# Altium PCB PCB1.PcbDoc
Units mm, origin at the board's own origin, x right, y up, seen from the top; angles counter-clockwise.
Board outline 152.4 x 101.6 mm, 2 copper layers (Top Layer, Bottom Layer); 41 components, 50 nets, 187 pads, 0 vias.
Unrouted connection lines stored in the file: 128.
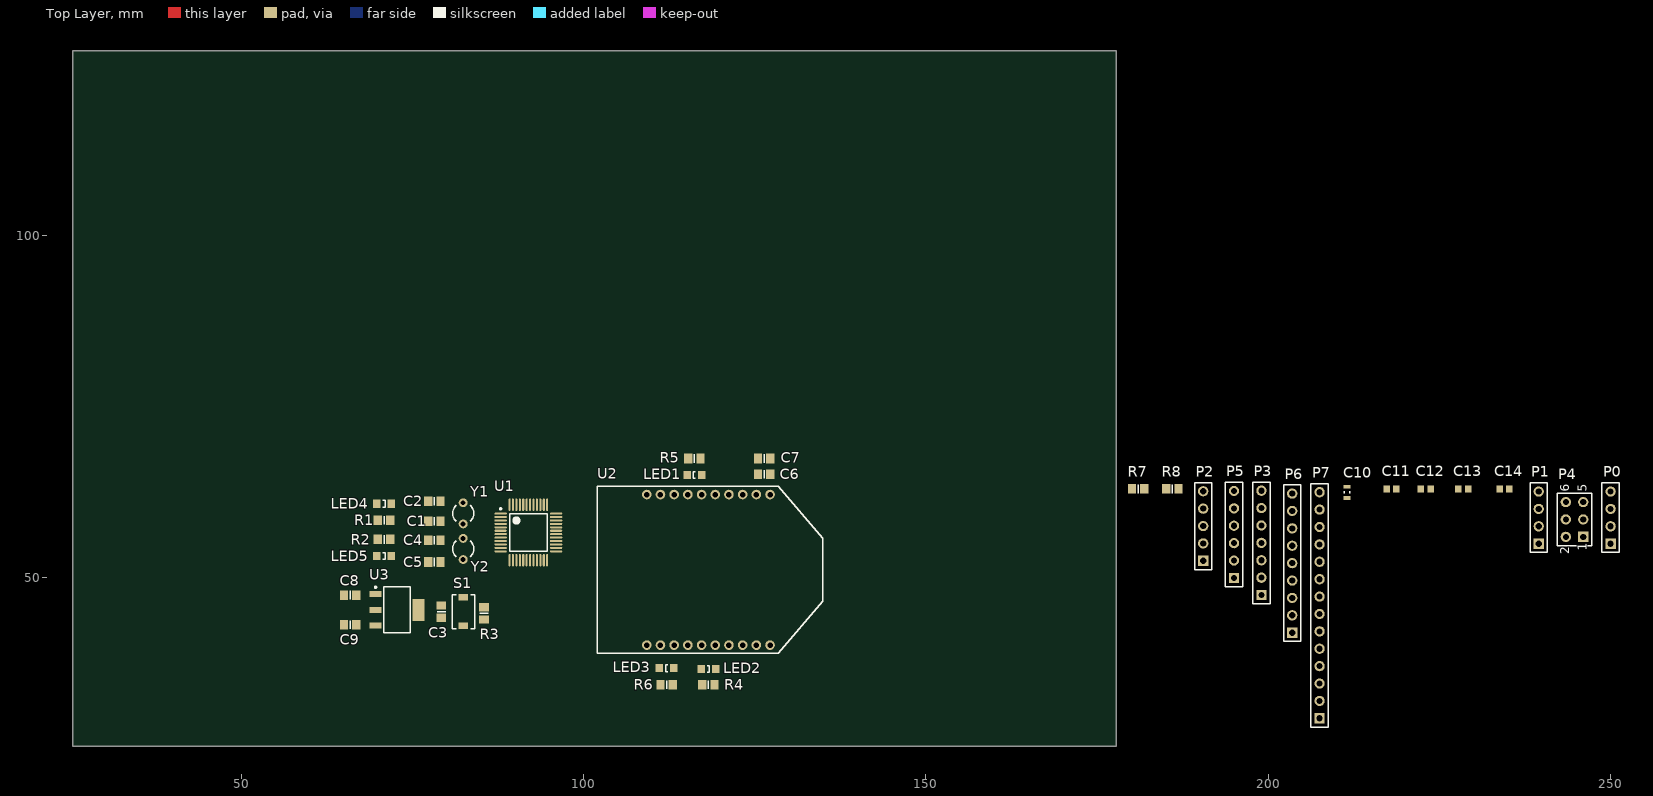
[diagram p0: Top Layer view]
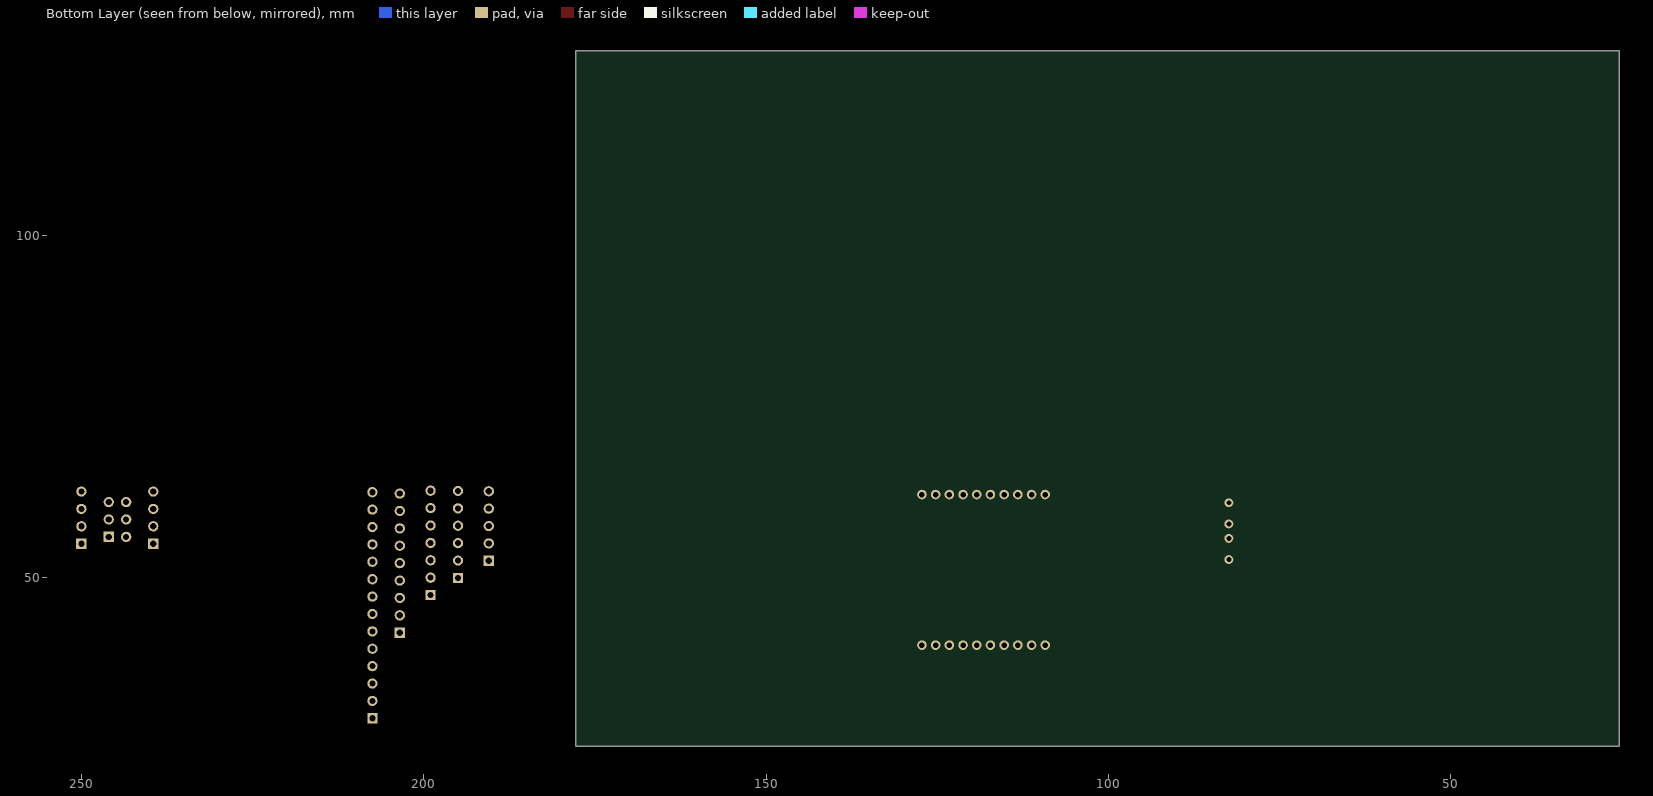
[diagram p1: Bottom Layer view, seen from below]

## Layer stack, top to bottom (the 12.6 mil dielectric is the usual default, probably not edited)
Top Solder: solder mask 0.0102, Solder Resist, Dk 3.5
Top Layer: signal copper 0.0356
Dielectric 1: dielectric 0.32, FR-4, Dk 4.8
Bottom Layer: signal copper 0.0356
Bottom Solder: solder mask 0.0102, Solder Resist, Dk 3.5

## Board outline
25.4,25.4 177.8,25.4 177.8,127 25.4,127

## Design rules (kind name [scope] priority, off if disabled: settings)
Clearance [All] p1: gap=0.254 ignorepadtopadclearanceinfootprint=FALSE except(0: Arc-Hole Track-Hole SMDPad-Hole THPad-Hole Via-Hole Fill-Hole Poly-Hole Region-Hole Text-Hole)
PolygonConnect [All] p1: connectstyle=Relief reliefconductorwidth=0.254 reliefentries=4 polygonreliefangle="90 Angle" airgapwidth=0.254
RoomDefinition Sheet1 [InComponentClass('Sheet1')] p1: confinementstyle=ConfineIn formatcopy=TRUE lockcomponents=FALSE outline 179,28 251.999,28 251.999,67 179,67
RoutingVias [All] p1: holewidth=0.711 width=1.27 viastyle="Through Hole" minholewidth=0.711 minwidth=1.27 maxholewidth=0.711 maxwidth=1.27
SolderMaskExpansion [All] p1: expansion=0.102
Width [All] p1: maxlimit=0.254 minlimit=0.254 preferedwidth=0.254
30 further rules are at their usual default settings.

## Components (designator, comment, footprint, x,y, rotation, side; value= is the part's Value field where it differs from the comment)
C1 "Cap" 6-0805_N 78.232,58.293 r180 top value=100pF
C2 "Cap" 6-0805_N 78.232,61.214 r180 top value=100pF
C3 "Cap" 6-0805_N 79.248,45.085 r90 top value=100pF
C4 "Cap" 6-0805_N 78.232,55.499 r0 top value=100pF
C5 "Cap" 6-0805_N 78.232,52.324 r0 top value=100pF
C6 "Cap" 6-0805_N 126.365,65.151 r0 top value=100pF
C7 "Cap" 6-0805_N 126.365,67.437 r0 top value=100pF
C8 "Cap" 6-0805_N 65.913,47.498 r0 top value=10uF
C9 "Cap" 6-0805_N 65.913,43.18 r0 top value=10uF
C10 "1 µF" CAPC1609X100X15NL20 211.5,62.5 r90 top
C11 "100 nF" SAMS-C0603-2_M 218,63 r0 top
C12 "100 nF" SAMS-C0603-2_M 223,63 r0 top
C13 "100 nF" SAMS-C0603-2_M 228.5,63 r0 top
C14 "100 nF" SAMS-C0603-2_M 234.5,63 r0 top
LED1 "150080SS75000" 0805_A 116.205,65.024 r0 top
LED2 "150080SS75000" 0805_A 118.237,36.703 r180 top
LED3 "150080SS75000" 0805_A 112.141,36.83 r0 top
LED4 "150080SS75000" 0805_A 70.866,60.833 r180 top
LED5 "150080SS75000" 0805_A 70.866,53.213 r180 top
P0 "Power" HDR1X4 249.999,55 r90 top
P1 "Prog" HDR1X4 239.5,55 r90 top
P2 "GY-61" HDR1X5 190.5,52.5 r90 top
P3 "MPL3115A2" HDR1X7 199,47.5 r90 top
P4 "BootSel" HDR2X3 246,56 r90 top
P5 "SDCard" HDR1X6 195,50 r90 top
P6 "Header 9" HDR1X9 203.5,42 r90 top
P7 "Header 14" HDR1X14 207.5,29.5 r90 top
R1 "Res1" 6-0805_N 70.866,58.42 r0 top value=1K
R2 "Res1" 6-0805_N 70.866,55.626 r0 top value=1K
R3 "Res1" 6-0805_N 85.471,44.831 r270 top value=10k
R4 "Res1" 6-0805_N 118.237,34.417 r0 top value=1K
R5 "Res1" 6-0805_N 116.205,67.437 r180 top value=1K
R6 "Res1" 6-0805_N 112.141,34.417 r180 top value=1K
R7 "Res1" 6-0805_N 181,63 r0 top value=2K
R8 "Res1" 6-0805_N 186,63 r0 top value=2K
S1 "SWITCH_2PIN" "SWITCH- TL1015AF160QG" 82.423,45.085 r270 top
U1 "STM32F103C8T6" STM-LQFP48_N 91.948,56.642 r0 top
U2 "XBP9B-DPST-001" DIP2200W51P200L3294H279Q20P 118.491,51.181 r270 top
U3 "TL1963A-33DCYR" DCY0004A_N 72.771,45.339 r0 top
Y1 "XTAL" R38 82.423,59.436 r0 top
Y2 "XTAL" R38 82.423,54.229 r180 top

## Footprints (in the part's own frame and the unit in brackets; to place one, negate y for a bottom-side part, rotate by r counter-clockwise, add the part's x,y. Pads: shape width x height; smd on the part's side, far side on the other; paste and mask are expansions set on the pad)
6-0805_N [mm] "Chip Resistor, Body 2.0x1.2mm, IPC Medium Density"
  rect 1.2x1.4 smd: 1(-0.9,0) 2(0.9,0)
  silkscreen extent 0,-0.6 0,0.6, body extent -1.07,-0.7 1.07,0.7, height 0.7
0805_A [mm] "Chip LED, 2-Leads, Body 2.0x1.3mm, IPC Medium Density"
  rect 1.1x1.2 smd: 1(-1.05,0) 2(1.05,0)
  silkscreen extent -0.15,-0.5 0.15,0.5, body extent -1,-0.62 1,0.63, height 0.68
CAPC1609X100X15NL20 [mm] "Chip Capacitor, 2-Leads, Body 1.60x0.85mm, IPC Medium Density"
  rect 0.55x1.05 smd: 1(-0.825,0) 2(0.825,0)
  silkscreen extent -0.15,-0.43 0.15,0.43, body extent -0.9,-0.53 0.9,0.53, height 1
DCY0004A_N [mm] "SOT223, 4-Leads, Body 6.7x3.7mm, Pitch 2.3mm, IPC Medium Density"
  rrect11% 1.75x0.9 smd: 1(-3.125,2.3) 2(-3.125,0) 3(-3.125,-2.3)
  rrect6% 1.75x3.2 smd: 4(3.125,0)
  silkscreen extent -3.25,-3.35 1.95,3.42, body extent -3.5,-3.25 3.5,3.25, height 1.62
DIP2200W51P200L3294H279Q20P [mm]
  round 1.4 hole 0.8: 1(-11,8.75) 2(-11,6.75) 3(-11,4.75) 4(-11,2.75) 5(-11,0.75) 6(-11,-1.25) 7(-11,-3.25) 8(-11,-5.25) 9(-11,-7.25) 10(-11,-9.25) 11(11,-9.25) 12(11,-7.25) 13(11,-5.25) 14(11,-3.25) 15(11,-1.25) 16(11,0.75) 17(11,2.75) 18(11,4.75) 19(11,6.75) 20(11,8.75)
  silkscreen extent -12.19,-16.47 12.19,16.47, body extent -12.18,-16.77 12.2,16.17, height 4.09
HDR1X4 [mm] "Connector; Header; 4 Position"
  rect 1.5x1.5 hole 0.9: 1(0,0)
  round 1.5 hole 0.9: 2(2.54,0) 3(5.08,0) 4(7.62,0)
  silkscreen extent -1.27,-1.27 8.89,1.27
HDR1X5 [mm] "Connector; Header; 5 Position"
  rect 1.5x1.5 hole 0.9: 1(0,0)
  round 1.5 hole 0.9: 2(2.54,0) 3(5.08,0) 4(7.62,0) 5(10.16,0)
  silkscreen extent -1.27,-1.27 11.43,1.27
HDR1X6 [mm] "Connector; Header; 6 Position"
  rect 1.5x1.5 hole 0.9: 1(0,0)
  round 1.5 hole 0.9: 2(2.54,0) 3(5.08,0) 4(7.62,0) 5(10.16,0) 6(12.7,0)
  silkscreen extent -1.27,-1.27 13.97,1.27
HDR1X7 [mm] "Connector; Header; 7 Position"
  rect 1.5x1.5 hole 0.9: 1(0,0)
  round 1.5 hole 0.9: 2(2.54,0) 3(5.08,0) 4(7.62,0) 5(10.16,0) 6(12.7,0) 7(15.24,0)
  silkscreen extent -1.27,-1.27 16.51,1.27
HDR1X9 [mm] "Connector; Header; 9 Position"
  rect 1.5x1.5 hole 0.9: 1(0,0)
  round 1.5 hole 0.9: 2(2.54,0) 3(5.08,0) 4(7.62,0) 5(10.16,0) 6(12.7,0) 7(15.24,0) 8(17.78,0) 9(20.32,0)
  silkscreen extent -1.27,-1.27 21.59,1.27
HDR1X14 [mm] "Connector; Header; 14 Position"
  rect 1.5x1.5 hole 0.9: 1(0,0)
  round 1.5 hole 0.9: 2(2.54,0) 3(5.08,0) 4(7.62,0) 5(10.16,0) 6(12.7,0) 7(15.24,0) 8(17.78,0) 9(20.32,0) 10(22.86,0) 11(25.4,0) 12(27.94,0) 13(30.48,0) 14(33.02,0)
  silkscreen extent -1.27,-1.27 34.29,1.27
HDR2X3 [mm] "Connector; Header; 3x2 Position"
  rect 1.5x1.5 hole 0.9: 1(0,0)
  round 1.5 hole 0.9: 2(0,2.54) 3(2.54,0) 4(2.54,2.54) 5(5.08,0) 6(5.08,2.54)
  silkscreen extent -1.27,-1.27 6.35,3.81
R38 [mm] "Crystal, Thru-Hole; 2 Leads; Body 3.1 x 8.2 mm (Dia.xH)"
  round 1.3 hole 0.7: 1(0,1.55) 2(0,-1.55)
  silkscreen extent -1.55,-1.19 1.55,1.17
SAMS-C0603-2_M [mm] "Chip Capacitor, 2-Leads, Body 1.70x0.90mm, IPC Low Density"
  rect 0.95x1.05 smd: 1(-0.725,0) 2(0.725,0)
  body extent -0.85,-0.45 0.85,0.45, height 0.9
STM-LQFP48_N [mm] "QFP, 48-Leads, Body 7x7mm, Pitch 0.5mm, IPC Medium Density"
  oval 1.8x0.3 smd: 1(-4.05,2.75) 2(-4.05,2.25) 3(-4.05,1.75) 4(-4.05,1.25) 5(-4.05,0.75) 6(-4.05,0.25) 7(-4.05,-0.25) 8(-4.05,-0.75) 9(-4.05,-1.25) 10(-4.05,-1.75) 11(-4.05,-2.25) 12(-4.05,-2.75) 25(4.05,-2.75) 26(4.05,-2.25) 27(4.05,-1.75) 28(4.05,-1.25) 29(4.05,-0.75) 30(4.05,-0.25) 31(4.05,0.25) 32(4.05,0.75) 33(4.05,1.25) 34(4.05,1.75) 35(4.05,2.25) 36(4.05,2.75)
  oval 0.3x1.8 smd: 13(-2.75,-4.05) 14(-2.25,-4.05) 15(-1.75,-4.05) 16(-1.25,-4.05) 17(-0.75,-4.05) 18(-0.25,-4.05) 19(0.25,-4.05) 20(0.75,-4.05) 21(1.25,-4.05) 22(1.75,-4.05) 23(2.25,-4.05) 24(2.75,-4.05) 37(2.75,4.05) 38(2.25,4.05) 39(1.75,4.05) 40(1.25,4.05) 41(0.75,4.05) 42(0.25,4.05) 43(-0.25,4.05) 44(-0.75,4.05) 45(-1.25,4.05) 46(-1.75,4.05) 47(-2.25,4.05) 48(-2.75,4.05)
  silkscreen extent -4.17,-2.75 2.75,3.57, body extent -3.5,-3.5 3.5,3.5, height 1.6
"SWITCH- TL1015AF160QG" [mm]
  rect 0.95x1.4 smd: 1(-2.075,0) 2(2.075,0)
  silkscreen extent -2.47,-1.6 2.53,1.7, body extent -2.26,-1.4 2.24,1.5, height 2.05

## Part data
C1 C2 C3 C4 C5 C6 C7 C8 C9: "Capacitor"
C10: library part CMP-2006-00184-1, Manufacturer="AVX Interconnect / Elco", Part Number=TACL105K010XTA
C11 C12 C13 C14: library part CMP-2000-05332-1, "Multi-layer Ceramic Capacitor, -55 to 125 degC, 2-Pin SMD (0603), RoHS, Tape and Reel", Capacitance=0.1µF, Case Size/Dimension=0603, Dielectric=X7R, Manufacturer="Samsung Electro-Mechanics", Rated Voltage=50V, Tolerance (%)=±10%
LED1 LED2 LED3 LED4 LED5: library part CMP-1426-00010-1, "SMD mono-color Chip LED, WL-SMCW, Super Red", Color="Super Red", Manufacturer="Wuerth Elektronik"
P0: library part "Header 4", "Header, 4-Pin"
P1: library part "Header 4", "Programming header like on Blue Pill"
P2: library part "Header 5", "GY-61 breakout board"
P3: library part "Header 7", "Adafruit MPL3115A2 breakout board"
P4: library part "Header 3X2", "Header, 3-Pin, Dual row"
P5: library part "Header 6", "Header, 6-Pin"
P6: "Header, 9-Pin"
P7: "Header, 14-Pin"
R1 R2 R3 R4 R5 R6 R7 R8: "Resistor"
S1: Supplier Part Number 1=2292962
U1: "ARM Cortex-M3 32-bit MCU, 64 KB Flash, 20 KB Internal RAM, 37 I/Os, 48-pin LQFP, -40 to 85 degC, Tray", I/Os (High Current)=37, Operating Frequency(F) (Processor speed) (MHz)=72, Supplier Part Number 1=497-6063-ND, Supply Voltage(Vcc) min (V)=2
U2: "XBee-PRO 900HP _S3B_ Point2Multipoint, 900MHz, 250mW, RPSMA, 10Kbps", Package="Module Digi International"
U3: library part CMP-0395-00535-2, "Single Output Low Noise LDO, 1.5 A, Fixed 3.3 V Output, 2.1 to 20 V Input, 4-pin SOT-223 (DCY), -40 to 125 degC, Green (RoHS & no Sb/Br)", Manufacturer="Texas Instruments"
Y1 Y2: "Crystal Oscillator"

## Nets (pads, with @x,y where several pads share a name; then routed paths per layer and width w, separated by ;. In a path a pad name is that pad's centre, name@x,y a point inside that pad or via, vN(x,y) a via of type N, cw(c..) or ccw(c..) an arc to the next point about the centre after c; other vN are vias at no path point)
AccX: P2.2 U1.10
AccY: P2.3 U1.11
AccZ: P2.4 U1.12
BaroInt1: P3.5 U1.41
BaroInt2: P3.4 U1.45
BOOT0: P4.3 U1.44
BOOT1: P4.4 U1.20
DCLK: P1.2 U1.37
DIO: P1.3 U1.34
GND: C1.2 C2.2 C3.1 C4.1 C5.1 C6.1 C7.1 C8.1 C9.1 C10.1 C11.2 C12.2 C13.2 C14.2 LED5.1 P0.1 P0.2 P1.4 P2.5 P3.2 P4.5 P4.6 P5.6 P7.3 P7.4 P7.5 R4.1 R5.1 R6.1 S1.2 U1.8 U1.23 U1.35 U1.47 U2.10 U3.2 U3.4
MISO: P5.5 P6.4 U1.16
MOSI: P5.3 P6.5 U1.17
NetC8_2: C8.2 P0.3 P0.4 U3.1
NetLED1_1: LED1.1 R5.2
NetLED1_2: LED1.2 U2.6
NetLED2_1: LED2.1 R4.2
NetLED2_2: LED2.2 U2.15
NetLED3_1: LED3.1 R6.2
NetLED3_2: LED3.2 U2.13
NetLED4_2: LED4.2 R1.1
NetLED5_2: LED5.2 R2.1
NRST: C3.2 R3.1 S1.1 U1.7 U2.5
PA2: P6.1 U1.13
PA3: P6.2 U1.14
PA8: P6.6 U1.29
PA11: P6.7 U1.32
PA12: P6.8 U1.33
PA15: P6.9 U1.38
PB9: P7.8 U1.46
PB10: P7.9 U1.21
PB11: P7.10 U1.22
PB12: P7.11 U1.25
PB13: P7.12 U1.26
PB14: P7.13 U1.27
PB15: P7.14 U1.28
PC0: C4.2 U1.5 Y2.2
PC1: C5.2 U1.6 Y2.1
PC13: LED4.1 U1.2
PC14: C2.1 U1.3 Y1.1
PC15: C1.1 U1.4 Y1.2
RADIO_CTS: U1.19 U2.4
RADIO_RTS: U1.40 U2.16
RADIO_SLEEP: U1.39 U2.9
RX: U1.31 U2.2
SCL: P3.6 P7.6 R7.1 U1.42
SD_CS: P5.2 U1.18
SDA: P3.7 P7.7 R8.1 U1.43
SPI_CLK: P5.4 P6.3 U1.15
TX: U1.30 U2.3
VCC: C6.2 C7.2 C9.2 C10.2 C11.1 C12.1 C13.1 C14.1 P1.1 P2.1 P3.1 P4.1 P4.2 P5.1 P7.1 P7.2 R1.2 R2.2 R3.2 R7.2 R8.2 U1.1 U1.9 U1.24 U1.36 U1.48 U2.1 U2.14 U3.3
pads on no net: P3.3 U2.7 U2.8 U2.11 U2.12 U2.17 U2.18 U2.19 U2.20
